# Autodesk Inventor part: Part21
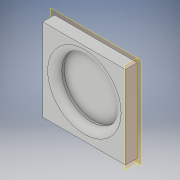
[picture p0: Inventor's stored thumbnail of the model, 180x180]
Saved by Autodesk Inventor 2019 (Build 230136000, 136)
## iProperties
Created: 2021-07
Part Number: Part21
Material: Generic
Document SubType Name: Modeling
Designer: Avinash
Density: 1 g/cm^3
Appearance: Default
Author: Avinash
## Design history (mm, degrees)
sketch "Sketch1"
  geometry: L1 (0, 0)-(-35, 0); L2 (-35, 0)-(-35, 35); L3 (-35, 35)-(0, 35); L4 (0, 35)-(0, 0)
  constraints: 8 end point, 2 parallel, 1 horizontal, 1 perpendicular
  dimensions: "d0" = 35 distance of L2.end L3.end; "d1" = 35 distance of L1.end L2.end
extrude "Extrusion1" new body sketch "Sketch1" distance "d2" = 5; taper "d3" = 0 deg
sketch "Sketch2"
  geometry: C1 r 12.525 at (-17.38, 18.141); 1 further point
  constraints: 1 centre point
  dimensions: "d4" = 25.05097 diameter of C1
extrude "Extrusion2" cut sketch "Sketch2" distance "d5" = 4; taper "d6" = 0 deg
fillet "Fillet1" dims "d7" = 3
body "Solid1"
